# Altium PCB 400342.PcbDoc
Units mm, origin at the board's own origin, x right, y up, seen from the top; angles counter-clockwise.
Board outline 64.3 x 23.1 mm, 2 copper layers (Top Layer, Bottom Layer), stack 1.271 mm thick; 34 components, 50 nets, 191 pads, 142 vias.
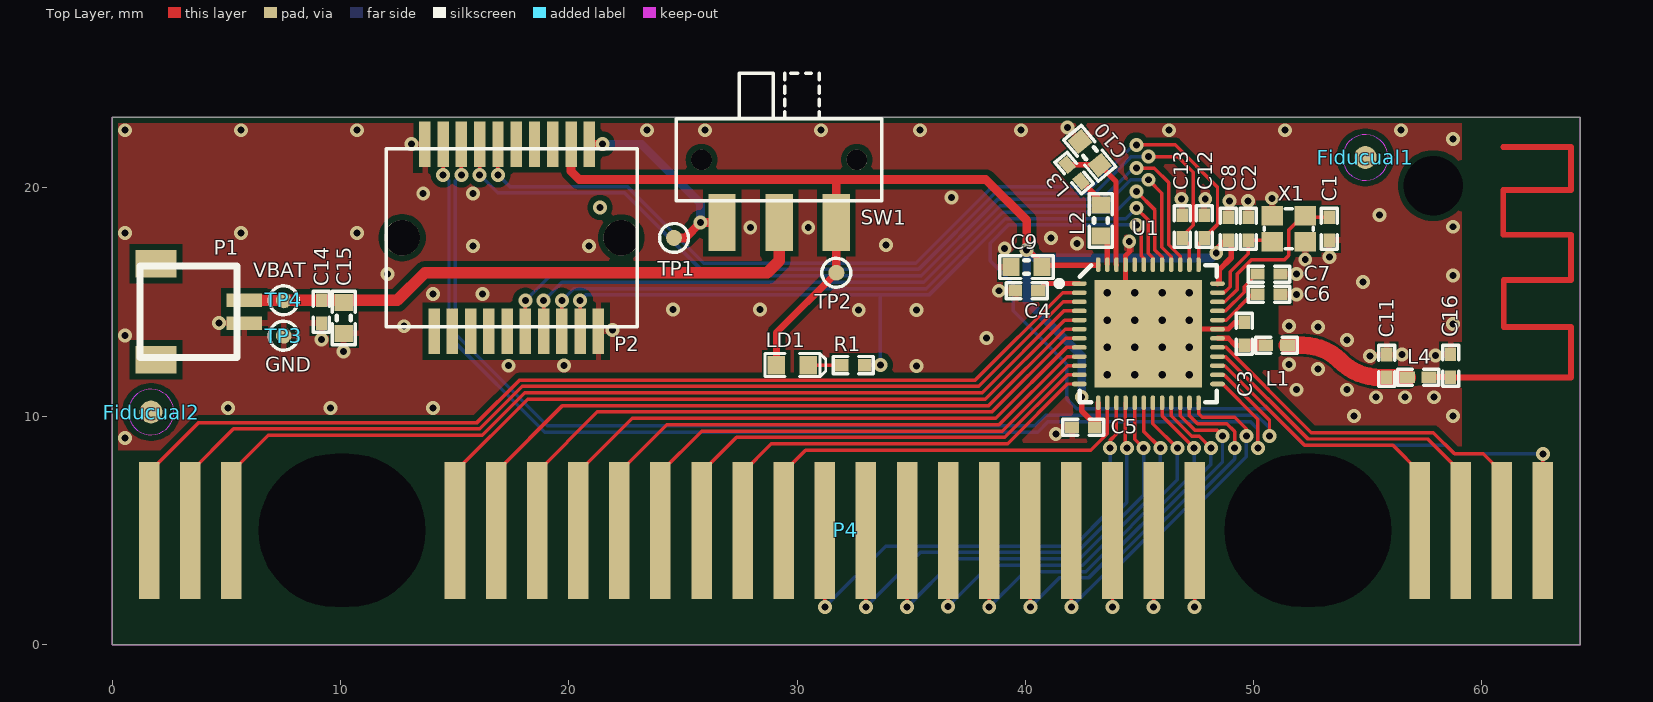
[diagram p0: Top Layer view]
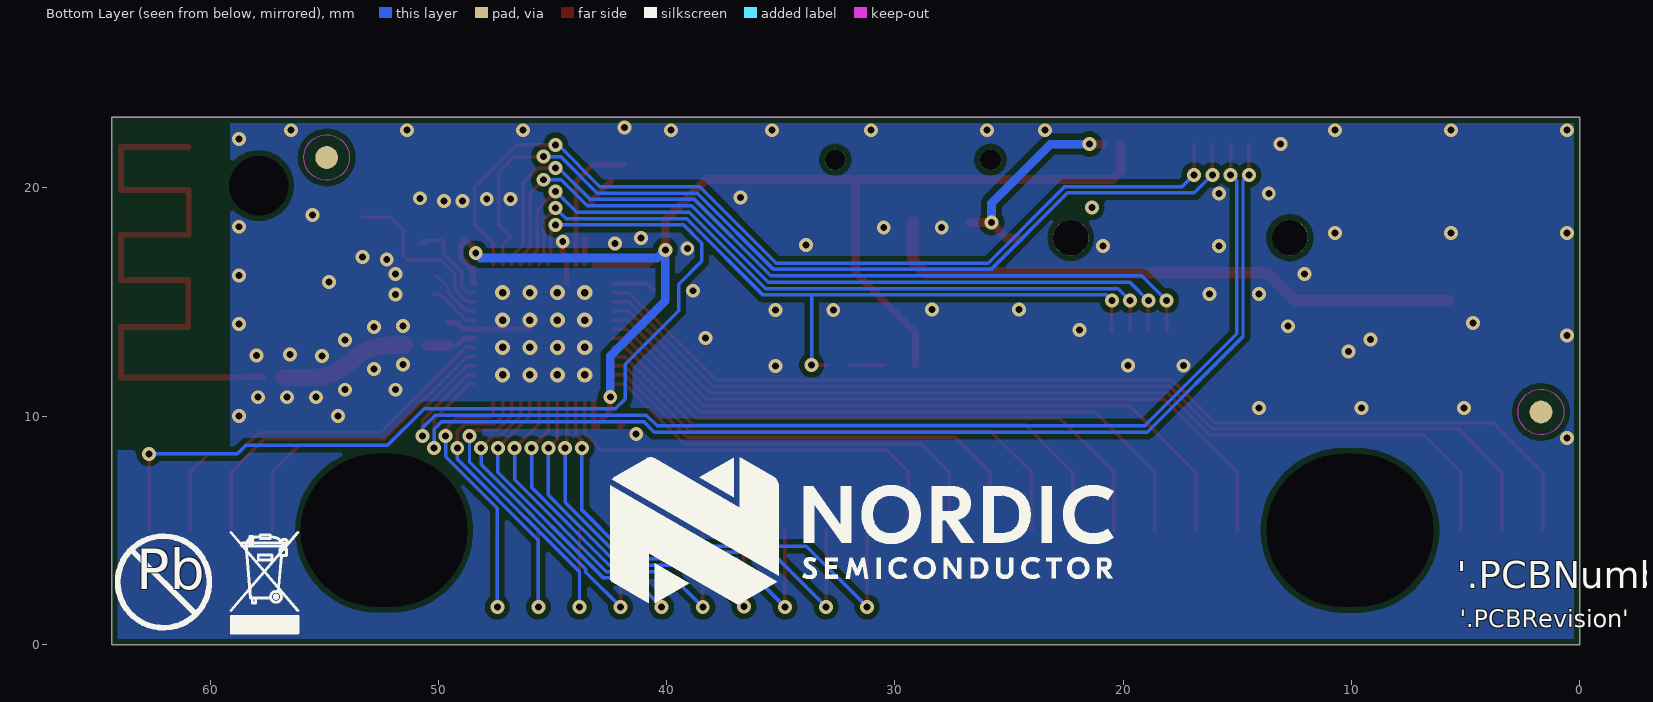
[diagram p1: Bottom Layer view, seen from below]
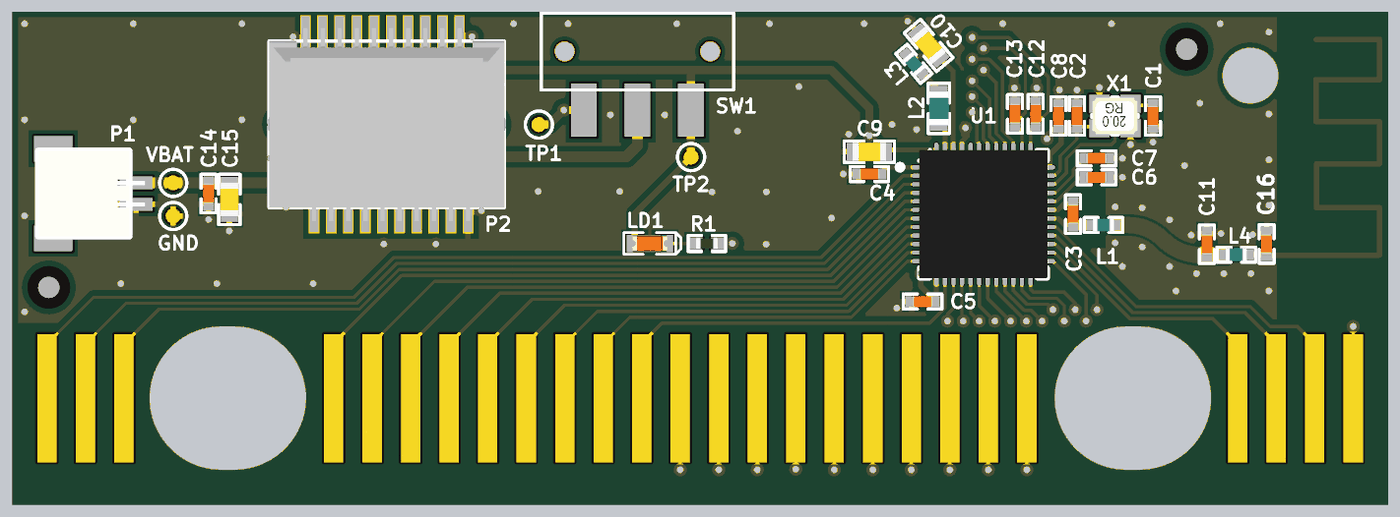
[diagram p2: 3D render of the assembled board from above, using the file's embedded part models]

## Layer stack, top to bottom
Top Solder: solder mask 0.0102, Solder Resist, Dk 3.5
Top Layer: signal copper 0.0356
Dielectric 1: dielectric 1.2, FR-4, Dk 4.8
Bottom Layer: signal copper 0.0356
Bottom Solder: solder mask 0.0102, Solder Resist, Dk 3.5

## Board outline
0,0 0,23.1 64.3,23.1 64.3,0

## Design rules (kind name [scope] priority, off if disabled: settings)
Clearance ANT_Clearance [InNet('ANT') or InNet('RF')] p1: gap=0.127 ignorepadtopadclearanceinfootprint=FALSE
Clearance Polygon_Clearance [(InNamedPolygon('Top_Layer-GND')) or (InNamedPolygon('Bottom_Layer-GND'))] p2: gap=0.254 ignorepadtopadclearanceinfootprint=FALSE except(0: Arc-Hole Track-Hole SMDPad-Hole THPad-Hole Via-Hole Fill-Hole Poly-Hole Region-Hole Text-Hole)
Clearance [All] p3: gap=0.127 ignorepadtopadclearanceinfootprint=FALSE except(0: Arc-Hole Track-Hole SMDPad-Hole THPad-Hole Via-Hole Fill-Hole Poly-Hole Region-Hole Text-Hole)
ComponentClearance [All] p1 off: gap=0.254 collisioncheckmode=3 verticalgap=0.254 showdistances=FALSE
DiffPairsRouting [All] p1: maxlimit=0.254 minlimit=0.19 mostfreqgap=0.193 toplayer_minwidth=0.165 toplayer_maxwidth=0.165 toplayer_prefwidth=0.165 bottomlayer_minwidth=0.165 bottomlayer_maxwidth=0.165 bottomlayer_prefwidth=0.165 maxuncoupledlength=12.7
HoleSize [All] p1: absolutevalues=TRUE maxlimit=7.62 minlimit=0.1 maxpercent=80.000 minpercent=20.000
MinimumAnnularRing [All] p1 off: minimumring=0.152
MinimumSolderMaskSliver [All] p1 off: minsoldermaskwidth=0.254
NetAntennae [All] p1 off: netantennaetolerance=0
PolygonConnect PolygonConnect_1 [isVia and innet(gnd)] p1: connectstyle=Direct reliefconductorwidth=0.254 reliefentries=4 polygonreliefangle="90 Angle" airgapwidth=0.254
PolygonConnect [All] p2: connectstyle=Relief reliefconductorwidth=0.254 reliefentries=4 polygonreliefangle="90 Angle" airgapwidth=0.254
RoutingVias [All] p1: holewidth=0.305 width=0.61 viastyle="Through Hole" minholewidth=0.1 minwidth=0.3 maxholewidth=0.33 maxwidth=1
SilkToSilkClearance [All] p1 off: silktosilkclearance=0.254
SilkToSolderMaskClearance [IsPad] p1 off: minsilkscreentomaskgap=0.254 clearancetoexposedcopper=TRUE
SolderMaskExpansion [All] p1: expansion=0.102
Width [All] p1: maxlimit=20 minlimit=0.1 preferedwidth=0.127 minimp=50.000000 maximp=50.000000 favimp=50.000000
23 further rules are at their usual default settings.

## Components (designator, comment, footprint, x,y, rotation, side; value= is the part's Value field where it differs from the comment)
C1 "12pF" CAPC1005X04L 53.312,18.211 r270 top
C2 "12pF" CAPC1005X04L 49.756,18.211 r90 top
C3 "0.8pF" CAPC1005X04L 49.578,13.613 r270 top
C4 "100nF" CAPC1005X04L 40.053,15.493 r180 top
C5 "100nF" CAPC1005X04L 42.542,9.524 r180 top
C6 "N.C." CAPC1005X04L 50.67,15.341 r180 top
C7 "100pF" CAPC1005X04L 50.67,16.23 r0 top
C8 "100nF" CAPC1005X04L 48.892,18.211 r90 top
C9 "4.7µF" CAPC1608X06L 40.053,16.534 r180 top
C10 "1.0µF" CAPC1608X06L 42.822,21.518 r310 top
C11 "1.2pF" CAPC1005X04L 55.832,12.206 r90 top
C12 "12pF" CAPC1005X04L 47.827,18.311 r90 top
C13 "12pF" CAPC1005X04L 46.862,18.311 r90 top
C14 "100nF" CAPC1005X04L 9.168,14.578 r90 top
C15 "1.0µF" CAPC1608X06L 10.143,14.303 r90 top
C16 "N.C." CAPC1005X04L 58.622,12.214 r270 top
Fiducual1 "Fiducial mark" Fiducial 54.889,21.336 r90 top
Fiducual2 "Fiducial mark" Fiducial 1.702,10.185 r90 top
L1 "3.9nH" INDC1005X04L 51,13.105 r0 top
L2 "10µH" INDC1608X06L 43.304,18.572 r270 top
L3 "15nH" INDC1005X04L 42.137,20.654 r310 top
L4 "1.5nH" INDC1005X04L 57.205,11.714 r0 top
LD1 "L0603R" LED_0603_R 29.794,12.243 r180 top
P1 "HDR-2, 1mm" SM02B-SRSS-TB 5.788,14.579 r270 top
P2 "Card Edge, 0.8mm" 10056847-101LF 17.499,17.82 r180 top
P4 "KBRFBE71_Keyboard_Connector" KBRFBE71_Keyboard_Connector 1.616,5 r0 top locked
R1 "100R" RESC1005X04L 32.461,12.243 r180 top
SW1 "Switch" JS102011SAQN 29.214,21.233 r180 top
TP1 "Ø0.7mm,SMD" TP_SMD_Ø0.7mm 24.608,17.81 r90 top
TP2 "Ø0.7mm,SMD" TP_SMD_Ø0.7mm 31.72,16.286 r90 top
TP3 "GND" TP_SMD_Ø0.7mm 7.516,13.529 r90 top value=Ø0.7mm,SMD
TP4 "VBAT" TP_SMD_Ø0.7mm 7.516,15.078 r90 top value=Ø0.7mm,SMD
U1 "nRF52832-QFAAE0" QFN40P600X600X90-48N 45.387,13.613 r0 top
X1 "32MHz" BT-XTAL_2016 51.534,18.211 r180 top

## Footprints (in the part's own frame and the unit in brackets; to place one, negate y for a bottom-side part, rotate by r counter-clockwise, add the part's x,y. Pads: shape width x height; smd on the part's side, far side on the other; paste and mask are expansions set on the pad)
10056847-101LF [mm]
  rect 0.5x2 smd paste-0.05 mask+0.025: 1(-3.4,-4.1) 2(-2.6,-4.1) 3(-1.8,-4.1) 4(-1,-4.1) 5(-0.2,-4.1) 6(0.6,-4.1) 7(1.4,-4.1) 8(2.2,-4.1) 9(3,-4.1) 10(3.8,-4.1) 11(3.4,4.1) 12(2.6,4.1) 13(1.8,4.1) 14(1,4.1) 15(0.2,4.1) 16(-0.6,4.1) 17(-1.4,4.1) 18(-2.2,4.1) 19(-3,4.1) 20(-3.8,4.1)
  round 1.55 hole 1.55 unplated mask+0: ""(-4.8,0) ""(4.8,0)
  silkscreen extent -5.5,-3.9 5.5,3.9, body extent -5.5,-4.5 5.5,4.53, height 5.28
BT-XTAL_2016 [mm] "Crystal 2.0 x 1.6 mm"
  rect 0.95x0.85 smd: 1(-0.725,-0.575) 2(0.725,-0.575) 3(0.725,0.575) 4(-0.725,0.575)
  silkscreen extent -1.08,-0.88 1.08,0.88, body extent -1.05,-0.85 1.05,0.85, height 0.56
CAPC1005X04L [mm] "Chip Capacitor, 2-Leads, Body 1.0x0.5mm, IPC High Density"
  rect 0.6x0.5 smd: 1(-0.5,0) 2(0.5,0)
  silkscreen extent -0.9,-0.35 0.9,0.35, body extent -0.51,-0.25 0.51,0.25, height 0.5
CAPC1608X06L [mm] "Chip Capacitor, 2-Leads, Body 1.6x0.8mm, IPC High Density"
  rect 0.75x0.8 smd: 1(-0.675,0) 2(0.675,0)
  silkscreen extent -1.17,-0.5 1.17,0.5, body extent -0.8,-0.43 0.8,0.43, height 0.8
Fiducial [mm] "Fiducial Mark"
  round 1 smd paste+0 mask+0.5: 0(0,0)
  round 1 smd far side paste+0 mask+0.5: 0(0,0)
  Top Layer keep-out circle w0.01: c0,0 r1
  Bottom Layer keep-out circle w0.01: c0,0 r1
INDC1005X04L [mm] "Chip Inductor, 2-Leads, Body 1.0x0.5mm, IPC High Density"
  rect 0.65x0.5 smd: 1(-0.475,0) 2(0.475,0)
  silkscreen extent -0.9,-0.35 0.9,0.35, body extent -0.5,-0.3 0.5,0.3, height 0.5
INDC1608X06L [mm] "Chip Inductor, 2-Leads, Body 1.6x0.8mm, IPC High Density"
  rect 0.75x0.8 smd: 1(-0.675,0) 2(0.675,0)
  silkscreen extent -1.17,-0.5 1.17,0.5, body extent -0.8,-0.48 0.8,0.48, height 0.8
JS102011SAQN [mm] "Slide Switches - SPDT, SMD, ON-ON"
  round 0.9 hole 0.9: 0(-3.4,0) 0(3.4,0)
  rect 1.2x2.5 smd: 1(-2.5,2.75) 2(0,2.75) 3(2.5,2.75)
  silkscreen extent -4.5,-3.8 4.5,1.8, body extent -4.52,-3.8 4.52,3.75, height 3.5
KBRFBE71_Keyboard_Connector [mm]
  rect 0.9x6 smd paste-0.508: 1(0,0) 2(1.8,0) 3(3.6,0) 4(13.4,0) 5(15.2,0) 6(17,0) 7(18.8,0) 8(20.6,0) 9(22.4,0) 10(24.2,0) 11(26,0) 12(27.8,0) 13(29.6,0) 14(31.4,0) 15(33.2,0) 16(35,0) 17(36.8,0) 18(38.6,0) 19(40.4,0) 20(42.2,0) 21(44,0) 22(45.8,0) 23(55.654,0) 24(57.454,0) 25(59.254,0) 26(61.054,0)
  rect 0.9x6 on Mech9 paste-0.508: 1(0,0) 2(1.8,0) 3(3.6,0) 4(13.4,0) 5(15.2,0) 6(17,0) 7(18.8,0) 8(20.6,0) 9(22.4,0) 10(24.2,0) 11(26,0) 12(27.8,0) 13(29.6,0) 14(31.4,0) 15(33.2,0) 16(35,0) 17(36.8,0) 18(38.6,0) 19(40.4,0) 20(42.2,0) 21(44,0) 22(45.8,0) 23(55.654,0) 24(57.454,0) 25(59.254,0) 26(61.054,0)
LED_0603_R [mil] "SMD Super Bright LED, RED"
  rect 30x32 smd: 1(-27.5,0) 2(27.5,0)
  silkscreen extent -58,-20 48,20, body extent -32,-16 32,16, height 24
QFN40P600X600X90-48N [mm] "QFN, 48-Leads, Body 6,0x6,0mm (max), Pitch 0,40mm, IPC Medium Density"
  oval 0.65x0.2 smd mask+0.05: 1(-3.025,2.2) 2(-3.025,1.8) 3(-3.025,1.4) 4(-3.025,1) 5(-3.025,0.6) 6(-3.025,0.2) 7(-3.025,-0.2) 8(-3.025,-0.6) 9(-3.025,-1) 10(-3.025,-1.4) 11(-3.025,-1.8) 12(-3.025,-2.2) 25(3.025,-2.2) 26(3.025,-1.8) 27(3.025,-1.4) 28(3.025,-1) 29(3.025,-0.6) 30(3.025,-0.2) 31(3.025,0.2) 32(3.025,0.6) 33(3.025,1) 34(3.025,1.4) 35(3.025,1.8) 36(3.025,2.2)
  oval 0.2x0.65 smd mask+0.05: 13(-2.2,-3.025) 14(-1.8,-3.025) 15(-1.4,-3.025) 16(-1,-3.025) 17(-0.6,-3.025) 18(-0.2,-3.025) 19(0.2,-3.025) 20(0.6,-3.025) 21(1,-3.025) 22(1.4,-3.025) 23(1.8,-3.025) 24(2.2,-3.025) 37(2.2,3.025) 38(1.8,3.025) 39(1.4,3.025) 40(1,3.025) 41(0.6,3.025) 42(0.2,3.025) 43(-0.2,3.025) 44(-0.6,3.025) 45(-1,3.025) 46(-1.4,3.025) 47(-1.8,3.025) 48(-2.2,3.025)
  rect 4.7x4.7 smd: 49(0,0)
  silkscreen extent -4.02,-3 3,3, body extent -3.02,-3.02 3.02,3.02, height 0.86
RESC1005X04L [mm] "Chip Resistor, 2-Leads, Body 1.0x0.5mm, IPC High Density"
  rect 0.6x0.55 smd: 1(-0.5,0) 2(0.5,0)
  silkscreen extent -0.87,-0.38 0.88,0.38, body extent -0.5,-0.25 0.5,0.25, height 0.3
SM02B-SRSS-TB [mm] "JST, SH connector, side entry SMD, 1mm pitch"
  rect 1.2x1.8 smd: 0(-2.1,-3.875) 0(2.1,-3.875)
  rect 0.6x1.55 smd: 1(-0.5,0) 2(0.5,0)
  silkscreen extent -2,-4.57 2,-0.33, body extent -1.99,-4.58 1.99,0.41, height 3
TP_SMD_Ø0.7mm [mm]
  round 0.7 smd paste-5: 1(0,0)
  silkscreen extent -0.63,-0.64 0.63,0.63

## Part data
C1 C2 C12 C13: library part C0402-12p, "Capacitor, NP0, ±2%", Part number IPS=00000002398
C3: library part C0402-0.8p, "Capacitor, NP0, ±5%", Part number IPS=00000007782
C4 C5 C8 C14: library part C0402-100n, "Capacitor, X7R, ±10%", Part number IPS=00000005296
C6 C16: library part C0402-N.C., "Not mounted", Part number IPS=N.A.
C7: library part C0402-100p, "Capacitor, NP0, ±5%", Part number IPS=00000002361
C9: library part C0603-4µ7, "Capacitor, X5R, ±10%", Part number IPS=00000007783
C10 C15: library part C0603-1µ0, "Capacitor, X7R, ±10%", Part number IPS=00000000616
C11: library part C0402-1.2p, "Capacitor, NP0, ±0.1pF", Part number IPS=00000005410
Fiducual1 Fiducual2: library part Fid-Mark, "Fiducial Mark", Part number IPS=N.A.
L1: library part L0402-3n9, "Inductor, 170mA, ±0.1nH", Manufacturer=Murata, Manufacturer Part Number=LQP15MN3N9B02D, Part number IPS=00000007793, Supplier Part Number 1=490-1131-1-ND
L2: library part L0603-10µ, "Inductor, 80mA, ±10%", Manufacturer="Taiyo Yuden", Manufacturer Part Number=LBMF1608T100K, Part number IPS=00000007794, Supplier Part Number 1=587-1714-1-ND
L3: library part L0402-15n, "Inductor, 320mA, ±5%", Manufacturer="Taiyo Yuden", Manufacturer Part Number=HK100515NJ-T, Part number IPS=00000001262, Supplier Part Number 1=587-1521-1-ND
L4: library part L0402-1n5, "Inductor, 280mA, ±0.1nH", Manufacturer=Murata, Manufacturer Part Number=LQP15MN1N5B02D, Part number IPS=N.A., Supplier Part Number 1=490-1126-1-ND
LD1: library part EL19-21SURC, "LED 0603, EL19-21SURC", Manufacturer=Everlight, Manufacturer Part Number=EL-19-21SURC/S530-A2/TR8, Part number IPS=N.A., Supplier Part Number 1=638-192SURCS530-A2
P1: library part SM02B-SRSS-TB, "1.0mm pitch connector side entry SMD", Manufacturer=JST, Manufacturer Part Number=SM02B-SRSS-TB(LF)(SN), Part number IPS=00000007791, Supplier Part Number 1=455-1802-1-ND
P2: library part 10056847-101LF, "0.8mm pitch, dual edge, right angle, SMD, card edge connector", Manufacturer=FCI, Part number IPS=N.A., Supplier Part Number 1=609-4943-1-ND
P4: "KBRFBE71 Keyboard Connector", Part number IPS=N.A.
R1: library part R0402-100, "Resistor, ±1%, 0.063W", Part number IPS=00000002811, Supplier Part Number 1=173-8837
SW1: library part JS102011SAQN, "SMD slide Switch (ON-ON)", Manufacturer="C&K Components", Part number IPS=N.A., Supplier Part Number 1=401-1999-1-ND
TP1 TP2 TP3 TP4: library part TP_SMD_Ø0.7MM, "0.7mm circular SMD testpad", Manufacturer="Nordic Semiconductor", Part number IPS=N.A.
U1: "Multi-protocol Bluetooth Low Energy, ANT and 2.4GHz proprietary system-on-chip", Manufacturer="Nordic Semiconductor", Part number IPS=N.A.
X1: library part XTAL_SMD2016_32MHz_8pF_KDS, "XTAL SMD 2016, 32MHz, Cl=8pF, Tol: ±10ppm, Stab: ±20ppm", Manufacturer=KDS, Manufacturer Part Number=DSX211G, Part number IPS=N.A.

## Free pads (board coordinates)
  rect 1.524x1.524 hole 6.7 slot 7.3 at 0 deg: ""(10.068,5.003) ""(52.372,5.003)
  round 1.524 hole 2.6: ""(57.866,20.1)

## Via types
v1: diameter 0.61, hole 0.305, Top Layer to Bottom Layer, tented both sides, 126 vias
v2: diameter 0.66, hole 0.33, Top Layer to Bottom Layer, tented both sides, 16 vias

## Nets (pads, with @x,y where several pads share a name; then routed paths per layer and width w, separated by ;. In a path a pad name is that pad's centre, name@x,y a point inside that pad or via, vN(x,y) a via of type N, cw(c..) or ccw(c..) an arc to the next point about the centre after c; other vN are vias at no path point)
ANT: C16.2 L4.2 | length 31
  Top Layer w0.254: L4.2@57.679,11.723 C16.2@58.576,11.723 ; C16.2@58.626,11.698 63.896,11.698 63.896,13.915 60.953,13.915 60.953,15.973 63.896,15.973 63.896,17.954 60.927,17.954 60.927,19.91 63.896,19.91 63.896,21.789 60.932,21.789
DEC1: C4.1 U1.1 | length 1.9
  Top Layer w0.203: C4.1@40.557,15.512 40.858,15.813 U1.1
DEC2: C6.2 U1.32 | length 2.2
  Top Layer w0.152: U1.32 48.798,14.213 49.925,15.341 C6.2@50.188,15.341
DEC3: C7.1 U1.33 | length 2.4
  Top Layer w0.152: U1.33 48.767,14.613 49.578,15.424 49.578,15.676 C7.1@50.062,16.16
DEC4: C10.2 L3.1 U1.46 | length 6.1
  Top Layer w0.229: L3.1 C10.2@43.239,21.018 ; C10.2 43.971,20.286 43.971,16.654 U1.46
GND: C1.2 C2.2 C3.1 C4.2 C5.2 C6.1 C7.2 C8.2 C9.2 C10.1 C11.2 C12.2 C13.2 C14.1 C15.1 C16.1 P1.2 P2.10 P2.20 TP3.1 U1.31 U1.45 U1.49 X1.2 X1.4 | length 5.7
  Top Layer w0.229: U1.49@44.387,15.813 U1.45 44.387,17.033 44.574,17.22 v1@44.574,17.652 ; U1.49@46.005,13.817 48.886,13.817 49.173,14.104 C3.1@49.586,14.104
  Top Layer w0.254: C5.2@41.959,9.607 C5.2
  other v1: 0.569,9.041 41.331,9.219 54.385,10.013 58.728,10.016 5.065,10.362 9.56,10.362 14.056,10.362 55.352,10.834 56.622,10.834 57.892,10.834 51.883,11.163 54.082,11.163 52.812,12.074 17.356,12.214 19.794,12.216 35.233,12.204 51.542,12.267 55.098,12.635 57.966,12.655 56.493,12.706 10.133,12.834 9.168,13.367 54.082,13.347 38.291,13.437 0.569,13.54 21.922,13.782 52.812,13.906 12.786,13.944 51.542,13.957 58.728,14.033 4.672,14.078 32.7,14.655 35.24,14.655 24.572,14.68 28.382,14.68 51.881,15.341 14.054,15.363 16.213,15.363 38.841,15.498 54.791,15.887 58.728,16.167 12.065,16.23 51.881,16.23 52.259,16.874 53.312,16.982 39.095,17.353 15.809,17.449 20.889,17.449 33.894,17.5 42.263,17.576 44.549,17.652 41.116,17.811 0.569,18.033 5.649,18.033 10.729,18.033 27.95,18.262 30.49,18.262 58.728,18.3 55.502,18.808 48.944,19.428 49.757,19.428 46.836,19.522 47.878,19.522 50.809,19.548 36.764,19.582 13.624,19.76 15.809,19.76 13.116,21.919 58.728,22.136 0.569,22.529 5.649,22.529 10.729,22.529 23.429,22.529 25.969,22.529 31.049,22.529 35.392,22.529 39.812,22.529 46.289,22.529 51.369,22.529 56.449,22.529 41.85,22.645
  other v2: 43.587,11.813 44.787,11.813 45.987,11.813 47.187,11.813 43.587,13.013 44.787,13.013 45.987,13.013 47.187,13.013 43.587,14.213 44.787,14.213 45.987,14.213 47.187,14.213 43.587,15.413 44.787,15.413 45.987,15.413 47.187,15.413
NetC3_2: C3.2 L1.1 U1.30 | length 2.2
  Top Layer w0.229: U1.30 48.887,13.413 49.197,13.104 C3.2@49.586,13.104
  Top Layer w0.508: C3.2@49.578,13.109 L1.1@50.475,13.109
NetL2_1: L2.1 L3.2 | length 1.4
  Top Layer w0.279: L3.2 43.304,19.428 L2.1
NetL2_2: L2.2 U1.47 | length 1.1
  Top Layer w0.229: U1.47@43.587,16.669 L2.2@43.587,17.817
NetLD1_1: LD1.1 R1.2 | length 1.5
  Top Layer w0.152: LD1.1 R1.2
P0.25: C12.1 P2.6 U1.37 | length 41.1
  Top Layer w0.152: v1(16.899,20.574) P2.6 ; v1(44.858,21.884) 46.56,21.884 48.415,20.029 48.415,18.399 47.587,17.571 U1.37
  Bottom Layer w0.152: v1(16.899,20.574) 17.411,20.062 22.555,20.062 25.908,16.709 35.2,16.709 38.546,20.055 42.921,20.055 44.749,21.884 v1(44.858,21.884)
P0.26: C13.1 P2.7 U1.38 | length 41
  Top Layer w0.152: v1@16.099,20.574 P2.7 ; v1(45.391,21.376) 46.666,21.376 47.35,20.693 47.35,18.367 C13.1@46.819,17.836 ; C13.1 47.187,17.486 U1.38
  Bottom Layer w0.152: v1(16.097,20.574) 16.889,19.783 22.439,19.783 25.792,16.43 35.316,16.43 38.662,19.776 43.036,19.776 44.637,21.376 v1(45.391,21.376)
P0.27: P2.16 U1.39 | length 36
  Top Layer w0.152: P2.16 v1(18.099,15.067) ; v1(44.858,20.868) 45.645,20.868 46.274,20.239 46.274,17.518 46.787,17.006 U1.39
  Bottom Layer w0.152: v1(18.099,15.067) 19.183,16.151 35.432,16.151 38.778,19.497 43.352,19.497 44.724,20.868 v1(44.858,20.868)
P0.28: P2.17 U1.40 | length 34.2
  Top Layer w0.152: P2.17 v1(18.899,15.067) ; v1(45.391,20.36) 45.975,19.777 45.975,17.394 46.387,16.982 U1.40
  Bottom Layer w0.152: v1@18.874,15.041 v1(18.899,15.067) 19.704,15.871 35.547,15.871 38.893,19.217 43.468,19.217 44.611,20.36 v1(45.391,20.36)
P0.29: P2.18 U1.41 | length 32.2
  Top Layer w0.152: P2.18 v1(19.699,15.067) ; v1(44.858,19.852) 45.676,19.035 45.676,17.27 45.987,16.959 U1.41
  Bottom Layer w0.152: v1(19.699,15.067) 20.224,15.592 35.663,15.592 39.009,18.938 43.944,18.938 v1(44.858,19.852)
P0.30: P2.19 R1.1 U1.42 | length 33.9
  Top Layer w0.152: P2.19 v1(20.499,15.067) ; R1.1 v1(33.647,12.243) ; v1(44.858,19.116) 45.376,18.597 45.376,17.146 45.587,16.936 U1.42
  Bottom Layer w0.152: v1(20.499,15.067) 20.745,15.312 33.668,15.312 ; v1(33.647,12.243) 33.647,15.292 33.668,15.312 ; v1(44.858,19.116) 44.401,18.658 39.125,18.658 35.779,15.312 33.668,15.312
R0: P4.26@62.67,5 U1.43 | length 41.7
  Top Layer w0.152: v1@45.077,18.185 45.077,17.022 45.187,16.912 U1.43 ; P4.26@62.67,5 v1(62.67,8.353)
  Bottom Layer w0.152: v1(44.858,18.379) 39.255,18.379 38.459,17.582 38.459,16.802 39.475,15.786 39.475,14.617 41.812,12.28 41.812,10.757 42.242,10.327 50.622,10.327 52.225,8.724 58.425,8.724 58.797,8.353 v1(62.67,8.353)
R1: P4.25@60.87,5 U1.29 | length 17.3
  Top Layer w0.152: U1.29 48.798,13.013 52.528,9.283 57.866,9.283 58.797,8.353 60.053,8.353 60.87,7.537 P4.25@60.87,5
R2: P4.24@59.07,5 U1.28 | length 15.3
  Top Layer w0.152: U1.28 48.767,12.613 52.377,9.004 57.626,9.004 59.07,7.56 P4.24@59.07,5
R3: P4.23@57.27,5 U1.27 | length 13.3
  Top Layer w0.152: U1.27 48.736,12.213 52.225,8.724 56.1,8.724 57.27,7.555 P4.23@57.27,5
R4: P4.21@45.616,5 U1.23 | length 15.3
  Top Layer w0.152: v1(45.616,1.647) P4.21@45.616,5 ; U1.23 47.187,10.03 47.541,9.676 48.823,9.676 49.169,9.33 v1(49.169,8.61)
  Bottom Layer w0.152: v1(45.616,1.647) 45.616,4.575 49.169,8.128 v1(49.169,8.61)
R5: P4.22@47.416,5 U1.24 | length 14.9
  Top Layer w0.152: v1(47.416,1.647) P4.22@47.416,5 ; U1.24@47.573,10.574 U1.24 47.587,10.115 47.746,9.956 49.169,9.956 49.677,9.448 v1(49.677,9.143)
  Bottom Layer w0.152: v1(47.416,1.647) 47.416,5.968 49.677,8.229 v1(49.677,9.143)
R6: P4.20@43.816,5 U1.22 | length 15.6
  Top Layer w0.152: v1(43.816,1.647) P4.20@43.816,5 ; U1.22 46.787,10.026 47.416,9.397 48.381,9.397 v1(48.635,9.143)
  Bottom Layer w0.147: v1(43.816,1.647) 43.816,3.182 48.635,8.001 v1(48.635,9.143)
R7: P4.19@42.016,5 U1.21 | length 15.7
  Top Layer w0.152: v1(42.016,1.647) P4.19@42.016,5 ; U1.21 46.387,10.016 47.286,9.118 47.619,9.118 v1(48.127,8.61)
  Bottom Layer w0.152: v1(42.016,1.647) 43.539,3.17 43.539,3.297 48.127,7.886 v1(48.127,8.61)
RF: C11.1 L1.2 L4.1 | length 5.6
  Top Layer w0.762: L1.2 52.155,13.105 cw(c52.155,10.814) 53.775,12.434 ccw(c55.553,14.213) 55.553,11.698 L4.1@56.729,11.698
S0: P4.18@40.216,5 U1.20 | length 16.6
  Top Layer w0.152: v1(40.216,1.647) P4.18@40.216,5 ; U1.20 45.987,10.013 v1(47.391,8.61)
  Bottom Layer w0.152: v1(40.216,1.647) 41.486,2.917 42.764,2.917 47.391,7.544 v1(47.391,8.61)
S1: P4.12@29.416,5 U1.14 | length 18.8
  Top Layer w0.152: P4.12@29.416,5 29.416,7.56 30.369,8.513 42.869,8.513 43.587,9.231 U1.14
S2: P4.10@25.816,5 U1.11 | length 20.9
  Top Layer w0.152: P4.10@25.816,5 25.816,7.541 27.346,9.072 39.103,9.072 41.845,11.813 U1.11
S3: P4.9@24.016,5 U1.10 | length 22.8
  Top Layer w0.152: P4.9@24.016,5 24.016,7.545 25.822,9.352 38.988,9.352 41.85,12.213 U1.10
S4: P4.8@22.216,5 U1.9 | length 24.8
  Top Layer w0.152: P4.8@22.216,5 22.216,7.548 24.298,9.631 38.844,9.631 41.826,12.613 U1.9
S5: P4.7@20.416,5 U1.8 | length 26.8
  Top Layer w0.152: P4.7@20.416,5 20.416,7.552 22.774,9.91 38.7,9.91 41.803,13.013 U1.8
S6: P4.6@18.616,5 U1.7 | length 28.7
  Top Layer w0.152: P4.6@18.616,5 18.616,7.555 21.25,10.19 38.539,10.19 41.763,13.413 U1.7
S7: P4.4@15.016,5 U1.5 | length 32.7
  Top Layer w0.152: P4.4@15.016,5 15.016,7.562 18.202,10.749 38.248,10.749 41.713,14.213 U1.5
S8: P4.5@16.816,5 U1.6 | length 30.7
  Top Layer w0.152: P4.5@16.816,5 16.816,7.558 19.726,10.469 38.395,10.469 41.739,13.813 U1.6
S9: P4.16@36.616,5 U1.18 | length 18.8
  Top Layer w0.152: v1(36.616,1.673) P4.16@36.616,5 ; U1.18@45.19,10.585 U1.18 45.191,9.331 v1(45.917,8.61)
  Bottom Layer w0.152: v1(36.616,1.673) 38.419,3.476 42.51,3.476 45.917,6.884 v1(45.917,8.61)
S10: P4.1@1.616,5 U1.2 | length 46.6
  Top Layer w0.152: P4.1@1.616,5 1.616,7.548 3.792,9.724 15.982,9.724 17.844,11.587 37.809,11.587 41.635,15.413 U1.2
S11: P4.2@3.416,5 U1.3 | length 44.6
  Top Layer w0.152: P4.2@3.416,5 3.416,7.544 5.316,9.445 16.097,9.445 17.96,11.307 37.96,11.307 41.666,15.013 U1.3
S12: P4.14@33.016,5 U1.16 | length 21.1
  Top Layer w0.152: v1(33.016,1.647) P4.14@33.016,5 ; U1.16@44.381,10.588 44.381,8.673 v1(44.444,8.61)
  Bottom Layer w0.152: v1(33.016,1.647) 35.403,4.035 42.256,4.035 44.444,6.223 v1(44.444,8.61)
S13: P4.15@34.816,5 U1.17 | length 19.9
  Top Layer w0.152: v1(34.816,1.647) P4.15@34.816,5 ; U1.17 44.793,8.995 v1(45.181,8.61)
  Bottom Layer w0.152: v1(34.816,1.647) 36.924,3.755 42.383,3.755 45.181,6.553 v1(45.181,8.61)
S14: P4.13@31.216,5 U1.15 | length 22.4
  Top Layer w0.152: v1(31.216,1.647) P4.13@31.216,5 ; v1(43.708,8.61) 43.708,8.94 43.987,9.219 U1.15
  Bottom Layer w0.152: v1(31.216,1.647) 33.883,4.314 42.129,4.314 43.708,5.893 v1(43.708,8.61)
S15: P4.11@27.616,5 U1.12 | length 18.9
  Top Layer w0.152: P4.11@27.616,5 27.616,7.538 28.87,8.793 39.219,8.793 41.84,11.413 U1.12
S16: P4.17@38.416,5 U1.19 | length 17.7
  Top Layer w0.152: v1(38.416,1.647) P4.17@38.416,5 ; U1.19 45.587,9.677 v1(46.654,8.61)
  Bottom Layer w0.152: v1(38.416,1.647) 39.965,3.197 42.637,3.197 46.654,7.214 v1(46.654,8.61)
S17: P4.3@5.216,5 U1.4 | length 42.6
  Top Layer w0.152: P4.3@5.216,5 5.216,7.541 6.84,9.166 16.213,9.166 18.075,11.028 38.104,11.028 41.69,14.613 U1.4
SWDCLK: P2.9 U1.25 | length 50.5
  Top Layer w0.152: v1(14.499,20.574) P2.9 ; U1.25 48.637,11.413 50.185,9.866 v1(50.185,8.61)
  Bottom Layer w0.152: v1(14.499,20.574) 14.753,20.32 14.753,13.492 18.944,9.301 40.533,9.301 41.001,9.769 49.854,9.769 50.185,9.438 v1(50.185,8.61)
SWDIO: P2.8 U1.26 | length 50.3
  Top Layer w0.152: v1(15.299,20.574) P2.8 ; U1.26 48.702,11.813 50.693,9.823 v1(50.693,9.143)
  Bottom Layer w0.152: v1(15.299,20.574) 15.033,20.308 15.033,13.608 19.06,9.58 40.417,9.58 40.884,10.048 50.134,10.048 50.693,9.489 v1(50.693,9.143)
VBAT: C14.2 C15.2 P1.1 SW1.2 TP4.1 | length 25.8
  Top Layer w0.508: P1.1 10.143,15.079 12.488,15.079 13.702,16.293 28.688,16.293 29.214,16.818 SW1.2
VDD_nRF: C5.1 C8.1 C9.1 LD1.2 P2.2 SW1.1 TP2.1 U1.13 U1.36 U1.48 | length 57.4
  Top Layer w0.229: v1@40.14,17.29 40.732,16.698 40.817,16.613 U1.48@43.177,16.613 ; C5.1@43.187,9.524 U1.13
  Top Layer w0.254: v1(42.467,10.843) 42.467,10.234 43.042,9.659 C5.1 ; v1(48.36,17.143) 48.36,17.289 48.782,17.711 C8.1 ; U1.36 48.486,15.887 48.486,16.405 49.021,16.939 49.021,17.455 C8.1@48.867,17.609
  Top Layer w0.305: LD1.2 29.096,13.661 TP2.1
  Top Layer w0.381: P2.2 20.099,20.732 20.464,20.367 31.723,20.367 ; TP2.1@31.714,16.293 SW1.1 31.714,20.357 31.723,20.367 ; v1(40.057,17.29) 40.057,18.58 38.27,20.367 31.723,20.367
  Bottom Layer w0.381: v1(42.467,10.843) 42.467,12.642 40.057,15.052 40.057,16.933 v1(40.057,17.29) 40.414,16.933 48.151,16.933 v1(48.36,17.143)
VDD_nRF': P2.1 SW1.3 TP1.1 | length 9.2
  Top Layer w0.381: P2.1 v1(21.483,21.92) ; TP1.1 25.1,17.81 v1(25.774,18.483) SW1.3
  Bottom Layer w0.381: v1(21.483,21.92) 23.186,21.92 25.774,19.333 v1(25.774,18.483)
XC1: C1.1 U1.34 X1.1 | length 7.5
  Top Layer w0.152: U1.34 48.736,15.013 49.27,15.548 49.27,16.05 49.27,16.216 49.919,16.865 51.356,16.865 51.534,17.042 51.534,18.16 52.085,18.711 C1.1
XC2: C2.1 U1.35 X1.3 | length 4.5
  Top Layer w0.152: U1.35 48.702,15.413 48.966,15.677 48.966,16.335 49.756,17.125 C2.1@49.756,17.659 ; C2.1 C2.1@49.756,17.659 ; X1.3@50.58,17.576 X1.3@50.797,17.576 ; X1.3@50.862,17.511 50.662,17.711 49.808,17.711 C2.1@49.756,17.659
pads on no net: Fiducual1.0 Fiducual2.0 P1.0 P2. P2.3 P2.4 P2.5 P2.11 P2.12 P2.13 P2.14 P2.15 P4.1@1.616,5 P4.2@3.416,5 P4.3@5.216,5 P4.4@15.016,5 P4.5@16.816,5 P4.6@18.616,5 P4.7@20.416,5 P4.8@22.216,5 P4.9@24.016,5 P4.10@25.816,5 P4.11@27.616,5 P4.12@29.416,5 P4.13@31.216,5 P4.14@33.016,5 P4.15@34.816,5 P4.16@36.616,5 P4.17@38.416,5 P4.18@40.216,5 P4.19@42.016,5 P4.20@43.816,5 P4.21@45.616,5 P4.22@47.416,5 P4.23@57.27,5 P4.24@59.07,5 P4.25@60.87,5 P4.26@62.67,5 SW1.0 U1.44
copper on no net:
  other v1: 21.369,19.148

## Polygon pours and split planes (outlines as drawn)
GND on Bottom Layer "Bottom_Layer-GND" (solid, remove dead copper, pour order 2): 66.05,-1.55 -1.539,-1.55 -1.539,25.221 66.05,25.221
GND on Top Layer "Top_Layer-GND" (solid, remove dead copper, pour order 0): 66.05,8.513 -1.539,8.513 -1.539,25.221 66.05,25.221

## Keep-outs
Keep-Out Layer:
  the board outline again, w0.013

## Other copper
Top Layer:
  pour cut-out: 64.768,25.668 59.103,25.668 59.103,8.508 64.768,8.508
  pour cut-out: 51.102,12.013 48.359,12.013 48.359,14.909 51.102,14.909
Bottom Layer:
  pour cut-out: 64.768,25.668 59.103,25.668 59.103,8.508 64.768,8.508

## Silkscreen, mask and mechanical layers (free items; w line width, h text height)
Bottom Overlay:
  drawing of 930 lines, arcs and shapes, not listed
  text "'.PCBNumber'" at 5.395,2.082 h2.03
  text "Pb" at 63.231,1.828 h3.05
  text "'.PCBRevision'" at 5.259,0.761 h0.76
Mechanical 1:
  the board outline again, w0.013
Mechanical 3:
  region: 72.14,0 71.973,1 72.306,1
  region: 72.306,22.1 71.973,22.1 72.14,23.1
  region: 64.3,34.985 63.3,34.819 63.3,35.152
  region: 1,34.819 0,34.985 1,35.152
  lines w0.013: 0,23.6 0,35.485 ; 1,34.985 63.3,34.985 ; 64.3,23.6 64.3,35.485 ; 64.8,0 72.64,0 ; 64.8,23.1 72.64,23.1 ; 72.14,1 72.14,22.1
  text "64.30" at 32.15,35.285 h1.5
  text "23.10" at 71.09,10.8 h1.5 r90
Mechanical 5:
  drawing of 154 lines, arcs and shapes, not listed
  text "1.20" at 96.462,24.377 h1.5
  text "Power connector}" at -27.808,11.738 h1.5
  text "LED}" at 22.437,11.521 h1.5
  text "Carbon}" at -18.122,1.885 h1.5
  text "S10,S11,S17,S7,S8,S6,S5,S4,S3,S2,S15,S1,S14,S12,S13,S9,S16,S0,R7,R6,R4,R5,R3,R2,R1,R0" at -10.974,-5.683 h1.15
  text "Height limitation 7.0mm}" at 8.595,-16.74 h1.5
Mechanical 6:
  circle w0.013: c57.866,-58.014 r1.3
  lines w0.013: 0,-47.444 64.3,-47.416 ; 3.347,-61.014 3.346,-59.027 4.046,-59.027 4.047,-61.014 ; 4.187,-61.014 47.096,-71.166 ; 33.087,-61.014 33.086,-59.014 33.786,-59.014 33.787,-61.014 48.096,-71.166 57.63,-61.014 ; 57.567,-61.014 57.566,-59.279 ; 58.166,-59.279 58.167,-61.014 ; 63.437,-42.34 68.242,-36.027 ; 0,-61.014 64.3,-61.014 64.3,-37.914 0,-37.914 0,-61.014 ; 9.77,-46.264 cw(c9.77,-42.914) 9.77,-39.564 10.37,-39.564 cw(c10.37,-42.914) 10.37,-46.264 9.77,-46.264 ; 52.07,-46.264 cw(c52.07,-42.914) 52.07,-39.564 52.67,-39.564 cw(c52.67,-42.914) 52.67,-46.264 52.07,-46.264
  text "Bottom" at 26.145,-34.959 h1.5
  text "Can't place component}" at 68.969,-35.264 h1.5
  text "Height limitation 8.0mm}" at 8.696,-51.544 h1.5
  text "Can't place component}" at 50.521,-70.393 h1.5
